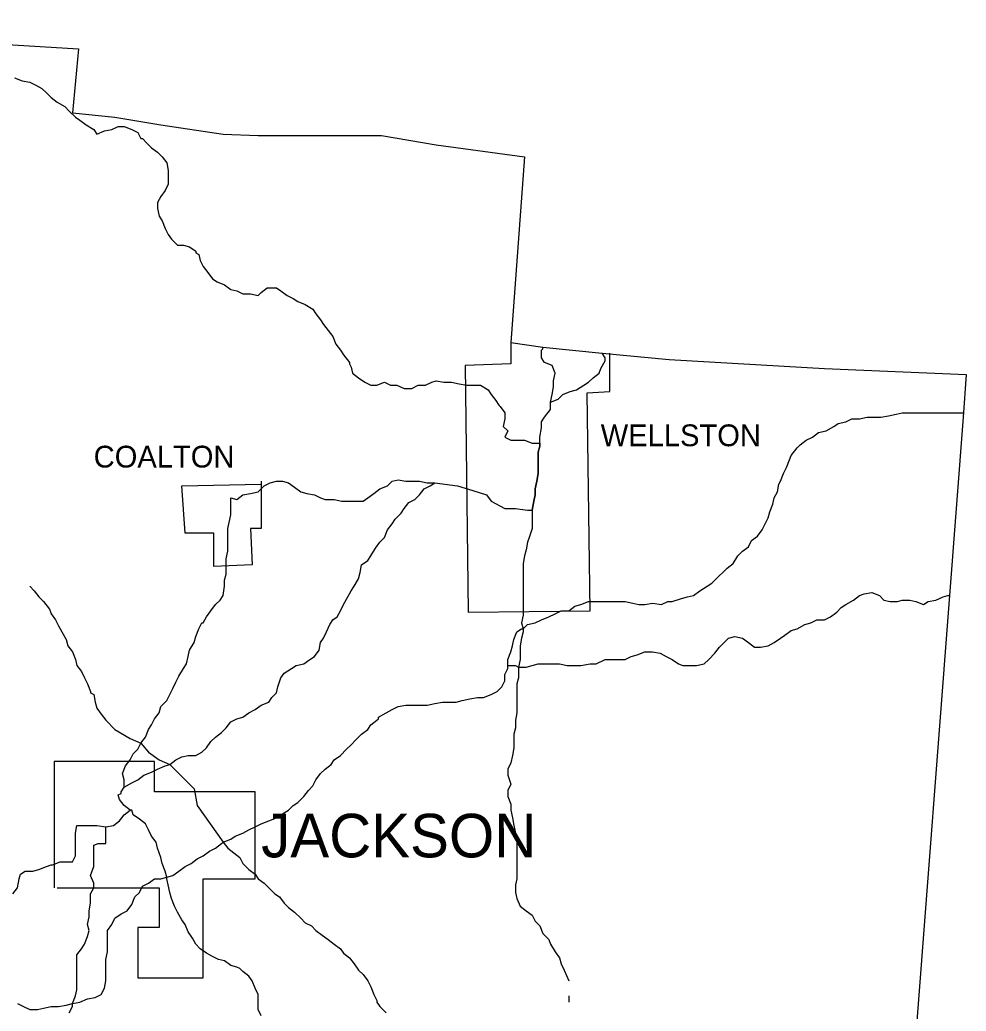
# Model space of a CAD drawing. Extents: x 0 to 34, y 0 to 22.
# Drawn here: x 7.227 to 8.075, y 17.615 to 18.503 of the extents above; entities that cross this region are included whole.
import ezdxf

# ---------------------------------------------------------------- set-up
doc = ezdxf.new("R2010")
doc.units = 0
doc.layers.add('Default', color=7, linetype='Continuous')

msp = doc.modelspace()

# ---------------------------------------------------------------- linework, layer by layer
at = {"layer": 'Default'}
for points in [[(6.88301, 18.50287), (7.05753, 18.4906), (7.13252, 18.48651), (7.1666, 18.48378), (7.27977, 18.47697), (7.27431, 18.4197), (7.31249, 18.41561), (7.35339, 18.4088), (7.40929, 18.40062), (7.44065, 18.39925), (7.49792, 18.39925), (7.55109, 18.39925), (7.60017, 18.39107), (7.67925, 18.38016), (7.66698, 18.21383)], [(7.2225, 18.45106), (7.22932, 18.44833), (7.23614, 18.44697), (7.24159, 18.44424), (7.24705, 18.44152), (7.25114, 18.43743), (7.25523, 18.43334), (7.26068, 18.42925), (7.2675, 18.42516), (7.27159, 18.42107), (7.27704, 18.41561), (7.28113, 18.41289), (7.28659, 18.4088), (7.2934, 18.40471), (7.29613, 18.40062), (7.30295, 18.40334), (7.30976, 18.40471), (7.31522, 18.40743), (7.32067, 18.40743), (7.32749, 18.40471), (7.33294, 18.40198), (7.33567, 18.39652)], [(7.33567, 18.39652), (7.33703, 18.39652), (7.33703, 18.39652), (7.34112, 18.39243), (7.34521, 18.38834), (7.35067, 18.38425), (7.35476, 18.38016), (7.35885, 18.37471), (7.36021, 18.36789), (7.36021, 18.36244), (7.36021, 18.35562), (7.35748, 18.35017), (7.35339, 18.34471), (7.35067, 18.33926), (7.35067, 18.33381), (7.35203, 18.32699), (7.35476, 18.3229), (7.35748, 18.31608), (7.36021, 18.31063), (7.36294, 18.30654), (7.36839, 18.30109), (7.37384, 18.30109), (7.3793, 18.29972), (7.38475, 18.29563)], [(7.38475, 18.29563), (7.38475, 18.29427), (7.38475, 18.29427), (7.38748, 18.2929), (7.38884, 18.28745), (7.39157, 18.282), (7.39566, 18.27654), (7.39975, 18.27109), (7.40384, 18.26836), (7.41066, 18.26564), (7.41611, 18.26155), (7.42156, 18.26018), (7.42702, 18.25746), (7.43383, 18.25746), (7.44065, 18.25609), (7.44338, 18.25882), (7.44883, 18.26291), (7.45701, 18.26291), (7.4611, 18.26018), (7.46656, 18.25609), (7.47201, 18.25337), (7.4761, 18.25064), (7.48292, 18.24791), (7.48973, 18.24382), (7.49246, 18.23973), (7.49655, 18.23428), (7.49928, 18.23019), (7.50337, 18.22473), (7.50746, 18.21928), (7.51019, 18.21246), (7.51428, 18.20701), (7.517, 18.20292), (7.52246, 18.1961)], [(7.66698, 18.21383), (7.66698, 18.19474), (7.62608, 18.19338), (7.6288, 17.9725), (7.73788, 17.97386), (7.73515, 18.16883), (7.7556, 18.1702), (7.7556, 18.20428)], [(7.66698, 18.21383), (7.69561, 18.20974), (7.74878, 18.20428), (7.80878, 18.19883), (7.94784, 18.19065), (8.07464, 18.18519)], [(7.70243, 18.16065), (7.70379, 18.16747), (7.70516, 18.17429), (7.70516, 18.17974), (7.70652, 18.18656), (7.70379, 18.19338), (7.69697, 18.1961), (7.69425, 18.20019), (7.69425, 18.20701), (7.69561, 18.20837), (7.69561, 18.20974)], [(7.52246, 18.1961), (7.52246, 18.19474), (7.52382, 18.19201), (7.52518, 18.18656), (7.53064, 18.18247), (7.53609, 18.17838), (7.54154, 18.17565), (7.547, 18.17565), (7.55382, 18.17838), (7.55927, 18.17565), (7.56472, 18.17565), (7.57154, 18.17292), (7.57836, 18.17292), (7.58381, 18.17565), (7.59063, 18.17565), (7.59608, 18.17838), (7.60017, 18.17974), (7.60699, 18.17838), (7.61381, 18.17838), (7.62062, 18.17701), (7.62744, 18.17565), (7.63426, 18.17565), (7.63971, 18.17565), (7.64653, 18.17156), (7.64926, 18.16747), (7.65335, 18.16202), (7.65607, 18.15793)], [(7.70243, 18.16065), (7.70925, 18.16338), (7.71334, 18.16747), (7.72015, 18.1702), (7.72561, 18.17156), (7.73242, 18.17565), (7.73651, 18.17838), (7.7406, 18.18247), (7.74606, 18.18656), (7.74742, 18.19065), (7.75151, 18.19747), (7.75151, 18.20019), (7.74878, 18.20428)], [(8.07464, 18.18519), (8.07192, 18.14702), (8.05964, 17.9875), (8.02965, 17.59483), (8.00783, 17.32079), (7.99011, 17.12309), (7.98875, 17.09991), (7.96693, 16.85722), (7.70107, 16.88313), (7.54564, 16.89676)], [(7.69288, 18.12384), (7.69288, 18.12929), (7.69425, 18.13747), (7.69425, 18.14293), (7.69697, 18.14702), (7.70243, 18.15384), (7.70243, 18.15929), (7.70243, 18.16065), (7.70243, 18.16065)], [(7.65607, 18.15793), (7.65744, 18.15656), (7.66153, 18.15111), (7.66153, 18.14566), (7.66016, 18.13884), (7.66425, 18.13475), (7.66153, 18.12929), (7.66698, 18.12657), (7.67243, 18.12657), (7.67925, 18.12657), (7.68607, 18.12384), (7.69288, 18.12384)], [(7.90831, 18.08976), (7.91103, 18.09657), (7.91376, 18.10203), (7.91649, 18.10884), (7.91785, 18.11293), (7.9233, 18.11975), (7.92603, 18.12248), (7.93148, 18.12657), (7.93694, 18.12929), (7.94239, 18.13338), (7.94921, 18.13475), (7.95602, 18.13884), (7.96012, 18.14157), (7.96693, 18.14293), (7.97239, 18.14566), (7.9792, 18.14566), (7.98602, 18.14702), (7.99147, 18.14702), (7.99829, 18.14702), (8.00511, 18.14838), (8.01193, 18.14975), (8.01738, 18.15111), (8.0242, 18.15111), (8.03101, 18.15111), (8.03647, 18.15111), (8.04328, 18.15111), (8.0501, 18.15111), (8.05692, 18.15111), (8.06374, 18.15111), (8.07055, 18.15111), (8.07192, 18.15111)], [(7.68607, 18.06385), (7.68743, 18.07203), (7.68879, 18.07748), (7.68879, 18.08294), (7.69016, 18.08976), (7.69152, 18.09657), (7.69152, 18.10203), (7.69152, 18.10884), (7.69152, 18.11566), (7.69288, 18.12111), (7.69288, 18.12384)], [(7.69288, 18.12384), (7.69288, 18.12111), (7.69152, 18.11566), (7.69152, 18.10884), (7.69152, 18.10203), (7.69152, 18.09657), (7.69016, 18.08976), (7.68879, 18.08294), (7.68879, 18.07748), (7.68743, 18.07203), (7.68607, 18.06385)], [(7.44338, 18.08976), (7.44338, 18.04749), (7.43383, 18.04749), (7.4352, 18.01477), (7.40111, 18.0134), (7.40111, 18.0434), (7.37521, 18.0434), (7.37248, 18.08566), (7.44338, 18.08703)], [(7.41611, 18.07476), (7.42156, 18.07339), (7.42702, 18.07748), (7.43383, 18.07885), (7.44065, 18.08021), (7.44611, 18.08566), (7.45156, 18.08839), (7.45701, 18.08976), (7.46247, 18.08976), (7.46792, 18.08839), (7.47337, 18.0843), (7.47883, 18.08021), (7.48428, 18.07885), (7.4911, 18.07748), (7.49655, 18.07476), (7.50064, 18.07339), (7.50201, 18.07339)], [(7.50201, 18.07339), (7.50882, 18.07339), (7.51564, 18.07203), (7.52246, 18.07203), (7.52927, 18.07203), (7.53473, 18.07203), (7.53882, 18.07476), (7.54427, 18.07885), (7.54973, 18.08294), (7.55654, 18.08566), (7.56063, 18.08976), (7.56609, 18.09112), (7.5729, 18.08976), (7.57972, 18.08976), (7.58517, 18.08976), (7.59199, 18.08839), (7.59881, 18.08839), (7.59881, 18.08839)], [(7.79378, 17.98068), (7.80196, 17.97932), (7.80741, 17.98204), (7.8115, 17.98204), (7.81968, 17.98477), (7.82514, 17.98614), (7.83059, 17.9875), (7.83604, 17.99159), (7.84286, 17.99568), (7.84695, 17.99841), (7.8524, 18.00386), (7.85786, 18.00931), (7.86059, 18.01204), (7.86604, 18.01613), (7.87013, 18.02295), (7.87422, 18.02704), (7.87967, 18.03113), (7.8824, 18.03658), (7.88785, 18.04067), (7.89194, 18.04613), (7.89467, 18.05158), (7.8974, 18.05703), (7.89876, 18.06249), (7.90149, 18.0693), (7.90285, 18.07476), (7.90558, 18.08021), (7.90694, 18.08703), (7.90831, 18.08976)], [(7.50473, 17.96159), (7.50746, 17.96568), (7.51155, 17.96841), (7.51428, 17.97386), (7.517, 17.97932), (7.52109, 17.98614), (7.52382, 17.99159), (7.52655, 17.99568), (7.53064, 18.0025), (7.532, 18.00795), (7.53336, 18.01477), (7.53882, 18.01886), (7.54154, 18.02295), (7.54564, 18.02976), (7.54973, 18.03522), (7.55382, 18.03931), (7.55654, 18.04613), (7.56063, 18.05158), (7.56336, 18.05567), (7.56881, 18.06112), (7.57154, 18.06521), (7.57563, 18.07067), (7.58108, 18.07339), (7.58517, 18.07748), (7.58926, 18.08294), (7.59472, 18.08566), (7.59881, 18.08839), (7.59881, 18.08839)], [(7.59881, 18.08839), (7.61926, 18.08566), (7.63289, 18.08157), (7.64516, 18.07748), (7.64926, 18.07203), (7.66153, 18.06521), (7.67107, 18.06521), (7.68198, 18.06385), (7.68607, 18.06385)], [(7.39157, 17.96296), (7.3943, 17.96841), (7.39839, 17.97386), (7.40248, 17.97932), (7.40657, 17.98341), (7.40929, 17.9875), (7.41066, 17.99568), (7.41066, 18.00113), (7.41202, 18.00659), (7.41202, 18.0134), (7.41202, 18.02022), (7.41338, 18.02704), (7.41338, 18.03385), (7.41338, 18.03931), (7.41338, 18.04749), (7.41475, 18.05294), (7.41611, 18.05976), (7.41611, 18.06521), (7.41611, 18.07203), (7.41611, 18.07339), (7.41611, 18.07476)], [(7.68607, 18.06385), (7.68607, 18.05976), (7.68607, 18.05294), (7.68607, 18.04749), (7.68334, 18.03931), (7.68198, 18.03522), (7.68061, 18.0284), (7.67925, 18.02295), (7.67789, 18.01613), (7.67789, 18.01068), (7.67789, 18.0025), (7.67789, 17.99568), (7.67789, 17.98886), (7.67789, 17.98341), (7.67789, 17.97659), (7.67789, 17.96977), (7.67652, 17.96296), (7.67789, 17.9575)], [(7.23614, 17.99568), (7.24023, 17.99159), (7.24432, 17.98614), (7.24841, 17.98204), (7.25386, 17.97523), (7.25523, 17.97114), (7.25932, 17.96568), (7.26204, 17.96023), (7.26477, 17.95478), (7.26886, 17.94796), (7.27022, 17.94251), (7.27431, 17.93705), (7.27704, 17.93023), (7.2784, 17.92478), (7.2825, 17.91933), (7.28522, 17.91387), (7.28795, 17.90842), (7.29068, 17.9016), (7.29068, 17.90024), (7.2934, 17.89888), (7.2934, 17.89888)], [(7.9124, 17.95205), (7.91785, 17.95614), (7.9233, 17.9575), (7.93012, 17.96159), (7.93557, 17.96296), (7.94103, 17.96568), (7.94784, 17.96568), (7.9533, 17.96841), (7.95875, 17.9725), (7.96284, 17.97659), (7.96693, 17.97932), (7.97375, 17.98341), (7.9792, 17.9875), (7.98329, 17.98886), (7.99011, 17.99023), (7.99693, 17.9875), (8.00102, 17.98341), (8.00647, 17.98204), (8.01329, 17.98204), (8.01738, 17.98341), (8.0242, 17.98341), (8.02965, 17.98204), (8.03647, 17.97932), (8.04056, 17.98204), (8.04737, 17.98341), (8.05419, 17.98614), (8.05828, 17.9875), (8.05828, 17.9875), (8.05964, 17.9875)], [(7.67789, 17.9575), (7.68198, 17.96159), (7.68879, 17.96296), (7.69425, 17.96568), (7.70107, 17.96841), (7.70652, 17.97114), (7.71197, 17.97386), (7.71879, 17.97386), (7.72424, 17.97795), (7.7297, 17.97932), (7.73651, 17.98204), (7.74197, 17.98204), (7.74742, 17.98204), (7.7556, 17.98204), (7.76242, 17.98204), (7.76924, 17.98204), (7.77605, 17.98068), (7.78151, 17.97932), (7.78696, 17.97932), (7.79378, 17.98068), (7.79378, 17.98068)], [(7.31931, 17.82798), (7.32203, 17.8348), (7.32612, 17.84025), (7.32885, 17.8457), (7.33294, 17.84979), (7.33567, 17.85525), (7.33976, 17.8607), (7.34249, 17.86752), (7.34521, 17.87161), (7.34794, 17.87706), (7.35203, 17.88252), (7.35339, 17.88797), (7.35885, 17.89342), (7.36157, 17.89888), (7.3643, 17.90433), (7.36703, 17.90978), (7.36975, 17.91524), (7.37384, 17.92205), (7.37657, 17.92614), (7.37793, 17.93296), (7.3793, 17.93842), (7.38339, 17.94523), (7.38475, 17.95069), (7.38748, 17.9575), (7.39021, 17.96296), (7.39157, 17.96296), (7.39157, 17.96296)], [(7.32067, 17.81571), (7.32749, 17.8198), (7.33294, 17.82252), (7.3384, 17.82661), (7.34521, 17.82934), (7.35067, 17.83207), (7.35748, 17.8348), (7.36157, 17.83616), (7.36703, 17.84025), (7.37248, 17.84298), (7.37793, 17.84434), (7.38475, 17.84434), (7.39021, 17.84707), (7.3943, 17.85116), (7.39839, 17.85661), (7.40248, 17.8607), (7.40793, 17.86479), (7.41202, 17.86888), (7.41611, 17.87433), (7.42156, 17.87706), (7.42702, 17.87842), (7.43247, 17.88252), (7.43793, 17.88524), (7.44338, 17.88933), (7.4502, 17.89206), (7.45292, 17.89615), (7.45701, 17.90024), (7.45838, 17.90569), (7.4611, 17.91387), (7.46383, 17.91796), (7.47065, 17.92205), (7.47474, 17.92478), (7.48155, 17.92614), (7.48701, 17.93023), (7.4911, 17.93296), (7.49519, 17.93842), (7.49655, 17.94523), (7.49928, 17.94932), (7.50201, 17.95478), (7.50473, 17.96159), (7.50473, 17.96159), (7.50473, 17.96159)], [(7.66425, 17.92478), (7.66425, 17.93023), (7.66698, 17.93705), (7.66834, 17.94251), (7.66971, 17.94796), (7.67243, 17.95478), (7.67652, 17.9575), (7.67789, 17.9575)], [(7.67789, 17.9575), (7.67789, 17.95478), (7.67652, 17.94932), (7.67516, 17.94251), (7.67516, 17.93705), (7.67516, 17.93023), (7.6738, 17.92342)], [(7.79378, 17.93705), (7.80059, 17.93569), (7.80605, 17.93296), (7.8115, 17.93023), (7.81696, 17.92614), (7.82105, 17.92478), (7.82786, 17.92478), (7.83332, 17.92478), (7.84013, 17.92614), (7.84422, 17.93023), (7.84968, 17.93569), (7.85377, 17.94114), (7.85786, 17.94523), (7.86195, 17.94932), (7.8674, 17.95069), (7.87422, 17.94932), (7.87967, 17.94523), (7.88513, 17.94114), (7.89058, 17.94114), (7.8974, 17.94251), (7.90285, 17.94523), (7.90831, 17.94932), (7.9124, 17.95205), (7.9124, 17.95205), (7.9124, 17.95205)], [(7.6738, 17.92342), (7.68061, 17.92342), (7.68607, 17.92478), (7.69152, 17.92614), (7.69834, 17.92614), (7.70516, 17.92614), (7.71061, 17.92614), (7.71743, 17.92478), (7.72288, 17.92478), (7.7297, 17.92478), (7.73788, 17.92614), (7.74333, 17.92614), (7.75151, 17.93023), (7.7556, 17.93023), (7.76242, 17.93023), (7.76924, 17.93023), (7.77469, 17.93296), (7.78014, 17.93433), (7.78696, 17.93705), (7.79241, 17.93705), (7.79378, 17.93705), (7.79378, 17.93705)], [(7.54836, 17.87842), (7.55518, 17.88252), (7.56063, 17.88524), (7.56609, 17.88797), (7.5729, 17.88933), (7.57972, 17.88933), (7.58517, 17.88933), (7.59199, 17.88933), (7.59881, 17.8907), (7.60563, 17.89206), (7.61244, 17.89206), (7.6179, 17.89206), (7.62335, 17.89342), (7.63017, 17.89479), (7.63698, 17.89615), (7.64244, 17.89615), (7.64926, 17.89888), (7.65471, 17.9016), (7.6588, 17.90569), (7.66153, 17.91115), (7.66153, 17.9166), (7.66425, 17.92205), (7.66425, 17.92478)], [(7.54836, 17.87842), (7.55518, 17.88252), (7.56063, 17.88524), (7.56609, 17.88797), (7.5729, 17.88933), (7.57972, 17.88933), (7.58517, 17.88933), (7.59199, 17.88933), (7.59881, 17.8907), (7.60563, 17.89206), (7.61244, 17.89206), (7.6179, 17.89206), (7.62335, 17.89342), (7.63017, 17.89479), (7.63698, 17.89615), (7.64244, 17.89615), (7.64926, 17.89888), (7.65471, 17.9016), (7.6588, 17.90569), (7.66153, 17.91115), (7.66153, 17.9166), (7.66425, 17.92205), (7.66425, 17.92478)], [(7.66425, 17.92478), (7.67107, 17.92478), (7.6738, 17.92342)], [(7.6738, 17.92342), (7.6738, 17.92205), (7.6738, 17.91387), (7.67243, 17.90842), (7.67243, 17.9016), (7.67243, 17.89615), (7.67243, 17.88933), (7.67243, 17.88252), (7.67107, 17.8757), (7.67107, 17.86888), (7.66971, 17.86343), (7.66971, 17.85661), (7.66971, 17.85116), (7.66834, 17.84434), (7.66698, 17.83752), (7.66425, 17.83207), (7.66425, 17.82661), (7.66698, 17.81843), (7.66425, 17.81298), (7.66425, 17.80753), (7.66698, 17.80071), (7.66698, 17.79526), (7.66834, 17.78844), (7.66971, 17.78162), (7.67107, 17.7748)], [(7.2934, 17.89888), (7.29477, 17.89206), (7.29613, 17.88661), (7.30022, 17.88115), (7.30431, 17.8757), (7.31249, 17.86752), (7.32612, 17.85934), (7.33567, 17.85525), (7.34249, 17.84707), (7.35203, 17.84025), (7.36157, 17.83616), (7.38339, 17.81434), (7.38612, 17.79935), (7.40929, 17.76662)], [(7.40929, 17.76662), (7.41611, 17.76935), (7.4202, 17.77208), (7.42702, 17.7748), (7.43247, 17.77753), (7.43793, 17.78026), (7.44338, 17.78299), (7.4502, 17.78571), (7.45701, 17.78844), (7.4611, 17.79117), (7.46792, 17.79526), (7.47201, 17.79935), (7.4761, 17.80207), (7.48155, 17.80753), (7.48564, 17.81298), (7.48973, 17.81707), (7.49246, 17.82252), (7.49655, 17.82798), (7.50064, 17.83207), (7.5061, 17.83616), (7.50882, 17.84025), (7.51428, 17.84434), (7.51973, 17.84979), (7.52382, 17.85388), (7.52791, 17.85797), (7.53336, 17.86343), (7.53882, 17.86752), (7.54154, 17.87161), (7.547, 17.8757), (7.54836, 17.87706), (7.54836, 17.87842)], [(7.40929, 17.76662), (7.41611, 17.76935), (7.4202, 17.77208), (7.42702, 17.7748), (7.43247, 17.77753), (7.43793, 17.78026), (7.44338, 17.78299), (7.4502, 17.78571), (7.45701, 17.78844), (7.4611, 17.79117), (7.46792, 17.79526), (7.47201, 17.79935), (7.4761, 17.80207), (7.48155, 17.80753), (7.48564, 17.81298), (7.48973, 17.81707), (7.49246, 17.82252), (7.49655, 17.82798), (7.50064, 17.83207), (7.5061, 17.83616), (7.50882, 17.84025), (7.51428, 17.84434), (7.51973, 17.84979), (7.52382, 17.85388), (7.52791, 17.85797), (7.53336, 17.86343), (7.53882, 17.86752), (7.54154, 17.87161), (7.547, 17.8757), (7.54836, 17.87706), (7.54836, 17.87842)], [(7.26068, 17.72572), (7.35203, 17.72572), (7.35203, 17.69027), (7.33294, 17.69027), (7.33294, 17.64528), (7.39157, 17.64528), (7.39157, 17.7339), (7.43793, 17.7339), (7.43793, 17.81162), (7.34794, 17.81162), (7.34794, 17.83889), (7.25795, 17.83889), (7.25795, 17.72572)], [(7.32067, 17.81571), (7.32067, 17.82252), (7.31931, 17.82798)], [(7.31794, 17.81025), (7.31794, 17.81162), (7.32067, 17.81571)], [(7.32612, 17.79526), (7.32067, 17.79935), (7.31658, 17.8048), (7.31522, 17.80889), (7.31794, 17.81025)], [(7.30431, 17.78026), (7.31113, 17.78162), (7.31658, 17.78571), (7.32067, 17.79117), (7.32612, 17.79526), (7.32612, 17.79526)], [(7.35885, 17.73527), (7.35748, 17.74072), (7.35476, 17.74754), (7.35339, 17.75299), (7.35067, 17.76117), (7.3493, 17.76662), (7.34521, 17.77208), (7.34249, 17.77753), (7.33976, 17.78299), (7.33431, 17.78708), (7.32885, 17.79117), (7.32749, 17.79526), (7.32612, 17.79526)], [(7.25659, 17.74617), (7.26341, 17.7489), (7.26886, 17.7489), (7.27431, 17.7489), (7.27704, 17.75435), (7.27704, 17.76117), (7.27704, 17.76799), (7.27704, 17.7748), (7.2784, 17.78162), (7.28522, 17.78162), (7.29068, 17.78162), (7.29613, 17.78162), (7.30431, 17.78026)], [(7.27431, 17.6221), (7.27704, 17.62892), (7.2784, 17.63437), (7.2784, 17.64119), (7.2784, 17.64801), (7.2784, 17.65482), (7.2784, 17.66028), (7.2784, 17.66573), (7.2825, 17.67118), (7.28522, 17.67528), (7.28795, 17.68209), (7.28931, 17.68755), (7.28795, 17.693), (7.28931, 17.69982), (7.28931, 17.70527), (7.29068, 17.71209), (7.29068, 17.72027), (7.2934, 17.72572), (7.2934, 17.72981), (7.29068, 17.73663), (7.2934, 17.74481), (7.2934, 17.75163), (7.2934, 17.75708), (7.2934, 17.7639), (7.29749, 17.76526), (7.30431, 17.76526), (7.30431, 17.77071), (7.30431, 17.77753), (7.30431, 17.7789), (7.30431, 17.78026)], [(7.67107, 17.7748), (7.67107, 17.7748), (7.67243, 17.77208), (7.67243, 17.76662), (7.67243, 17.75844), (7.67243, 17.75299), (7.67243, 17.74754), (7.67243, 17.74072), (7.67243, 17.7339), (7.67107, 17.72845), (7.67107, 17.72163), (7.67243, 17.71618), (7.67516, 17.70936), (7.68061, 17.70527), (7.68607, 17.70118), (7.68879, 17.69573), (7.69288, 17.69164), (7.69561, 17.68482), (7.70107, 17.67937), (7.70243, 17.67528), (7.70652, 17.66846), (7.71061, 17.663), (7.71197, 17.65755), (7.7147, 17.6521), (7.71879, 17.64255)], [(7.35885, 17.73527), (7.3643, 17.73663), (7.36975, 17.74072), (7.37521, 17.74481), (7.38066, 17.74754), (7.38612, 17.75163), (7.39157, 17.75435), (7.39702, 17.75844), (7.40248, 17.76117), (7.40793, 17.76526), (7.40929, 17.76662)], [(7.35885, 17.73527), (7.3643, 17.73663), (7.36975, 17.74072), (7.37521, 17.74481), (7.38066, 17.74754), (7.38612, 17.75163), (7.39157, 17.75435), (7.39702, 17.75844), (7.40248, 17.76117), (7.40793, 17.76526), (7.40929, 17.76662)], [(7.40929, 17.76662), (7.41338, 17.76117), (7.41884, 17.75708), (7.42429, 17.75299), (7.42702, 17.74754), (7.43247, 17.74208), (7.43793, 17.73799), (7.44065, 17.7339), (7.44611, 17.72981), (7.4502, 17.72572), (7.45565, 17.72027), (7.45974, 17.71754), (7.46383, 17.71209), (7.46792, 17.708), (7.47337, 17.70391), (7.47883, 17.69845), (7.48292, 17.69436), (7.48837, 17.69164), (7.49246, 17.68755), (7.49792, 17.68346), (7.50337, 17.67937), (7.50882, 17.67528), (7.51428, 17.67118), (7.517, 17.66709), (7.52246, 17.663), (7.52655, 17.65755), (7.53064, 17.6521), (7.53473, 17.64801), (7.53882, 17.64255), (7.54154, 17.6371), (7.54427, 17.63028), (7.547, 17.62483), (7.547, 17.62347)], [(7.22114, 17.72027), (7.22523, 17.72572), (7.22659, 17.7339), (7.22796, 17.73799), (7.23205, 17.74072), (7.23887, 17.74072), (7.24432, 17.74208), (7.25114, 17.74481), (7.25523, 17.74617), (7.25659, 17.74617)], [(7.27431, 17.6221), (7.28113, 17.62347), (7.28795, 17.62619), (7.29477, 17.62756), (7.30022, 17.63028), (7.30295, 17.63574), (7.30431, 17.64255), (7.30431, 17.64801), (7.30431, 17.65482), (7.30431, 17.66164), (7.30567, 17.66846), (7.30567, 17.67528), (7.30567, 17.68073), (7.30567, 17.68755), (7.30976, 17.693), (7.31249, 17.69845), (7.31794, 17.70254), (7.3234, 17.70527), (7.32749, 17.71072), (7.33021, 17.71754), (7.33431, 17.72163), (7.33703, 17.72709), (7.34249, 17.72981), (7.34794, 17.7339), (7.35339, 17.7339), (7.35885, 17.73527), (7.35885, 17.73527)], [(7.27431, 17.6221), (7.28113, 17.62347), (7.28795, 17.62619), (7.29477, 17.62756), (7.30022, 17.63028), (7.30295, 17.63574), (7.30431, 17.64255), (7.30431, 17.64801), (7.30431, 17.65482), (7.30431, 17.66164), (7.30567, 17.66846), (7.30567, 17.67528), (7.30567, 17.68073), (7.30567, 17.68755), (7.30976, 17.693), (7.31249, 17.69845), (7.31794, 17.70254), (7.3234, 17.70527), (7.32749, 17.71072), (7.33021, 17.71754), (7.33431, 17.72163), (7.33703, 17.72709), (7.34249, 17.72981), (7.34794, 17.7339), (7.35339, 17.7339), (7.35885, 17.73527), (7.35885, 17.73527)], [(7.42156, 17.65482), (7.41611, 17.65619), (7.41066, 17.66028), (7.4052, 17.66164), (7.39975, 17.66437), (7.3943, 17.66709), (7.38884, 17.67118), (7.38475, 17.67528), (7.38202, 17.68073), (7.37793, 17.68618), (7.37521, 17.693), (7.37248, 17.69709), (7.36839, 17.70391), (7.36566, 17.70936), (7.36294, 17.71618), (7.36157, 17.72163), (7.36021, 17.72845), (7.35885, 17.7339), (7.35885, 17.73527)], [(7.44338, 17.61119), (7.44065, 17.61665), (7.44065, 17.62347), (7.44065, 17.63028), (7.43793, 17.63574), (7.4352, 17.64255), (7.43247, 17.64664), (7.42702, 17.65073), (7.42429, 17.65346), (7.42156, 17.65482)], [(7.71879, 17.62892), (7.71879, 17.62347)], [(7.22523, 17.6221), (7.23069, 17.61937), (7.23614, 17.61665), (7.24296, 17.61665), (7.24841, 17.61801), (7.25523, 17.61937), (7.26204, 17.61937), (7.26886, 17.62074), (7.27431, 17.6221), (7.27431, 17.6221)], [(7.22523, 17.6221), (7.23069, 17.61937), (7.23614, 17.61665), (7.24296, 17.61665), (7.24841, 17.61801), (7.25523, 17.61937), (7.26204, 17.61937), (7.26886, 17.62074), (7.27431, 17.6221), (7.27431, 17.6221)], [(7.27159, 17.61392), (7.27431, 17.61937), (7.27431, 17.6221)], [(7.547, 17.62347), (7.54973, 17.61937), (7.55518, 17.61392)]]:
    msp.add_lwpolyline(points, dxfattribs=at)

# ---------------------------------------------------------------- texts
for s, height, p in [('WELLSTON', 0.019502, (7.74742, 18.12111)), ('COALTON', 0.019502, (7.2934, 18.10203)), ('JACKSON', 0.039005, (7.44338, 17.75299))]:
    msp.add_text(s, height=height, dxfattribs=at).set_placement(p)

doc.saveas('drawing.dxf')
